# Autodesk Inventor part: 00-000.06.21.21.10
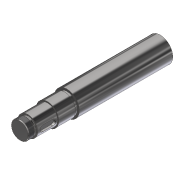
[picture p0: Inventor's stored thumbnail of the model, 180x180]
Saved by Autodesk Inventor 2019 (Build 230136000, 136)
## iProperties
Created: 2019-01
Part Number: 00-000.06.21.21.10
Material: Steel, Mild
Document SubType Name: Modeling
Designer: m.vorobev
Density: 7.85 g/cm^3
Appearance: Semi-Polished
Author: m.vorobev
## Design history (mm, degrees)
sketch "Sketch1"
  geometry: L1 (0, 0)-(18, 0); L2 (18, 0)-(18, -11.5); L3 (18, -11.5)-(0, -11.5); L4 (0, -11.5)-(0, 0); L5 (0, -16)-(20, -16); L6 (20, -16)-(20, -55.5); L7 (20, -55.5)-(0, -55.5); L8 (0, -55.5)-(0, -16); L9 (0, -55.5)-(22.5, -55.5); L10 (22.5, -55.5)-(22.5, -89); L11 (22.5, -89)-(0, -89); L12 (0, -89)-(0, -55.5); L13 (0, -89)-(21, -89); L14 (21, -89)-(21, -94); L15 (21, -94)-(0, -94); L16 (0, -94)-(0, -89); L17 (0, -94)-(25, -94); L18 (25, -94)-(25, -280.744); L19 (25, -280.744)-(0, -280.744); L20 (0, -280.744)-(0, -94); L21 (18, -11.5)-(16.8, -12.7); L22 (16.8, -12.7)-(16.8, -16); L23 (0, -11.5)-(0, -16)
  constraints: 46 end point, 10 parallel, 6 perpendicular, 5 horizontal, 2 point on line, 1 collinear
  dimensions: "d0" = 36 diameter of L2 L4; "d1" = 16 distance between parallel lines of L5 L1; "d2" = 4.5 distance between parallel lines of L5 L3; "d3" = 33.6 diameter of L22 L4; "d4" = 45 deg angle of L2 L21; "d5" = 40 diameter of L6 L4; "d6" = 45 diameter of L10 L4; "d7" = 39.5 distance of L5.end L6.end; "d8" = 94 distance between parallel lines of L1 L17; "d9" = 42 diameter of L14 L4; "d10" = 50 diameter of L18 L4; "d11" = 5 distance of L13.end L14.end
revolve "Revolution1" sketch "Sketch1" stored, may be unused: angle "d12" = 90 deg
fillet "Fillet1" dims "d13" = 0.8
chamfer "Chamfer1" distance "d14" = 1.6; stored, may be unused: second distance "d15" = 2, angle "d16" = 45 deg
workplane "Work Plane1"
sketch "Sketch2"
  geometry: L1 (0, 14.75)-(0, -17.25); L2 (6, 8.75)-(6, -11.25); L3 (-6, -11.25)-(-6, 8.75); L4 (-20, 19.75)-(20, 19.75) reference; L5 (-22.5, -19.75)-(22.5, -19.75) reference; A1 r 6 centre (0, 8.75) between (6, 8.75) and (-6, 8.75); A2 r 6 centre (0, -11.25) between (-6, -11.25) and (6, -11.25); 2 further points
  constraints: 8 end point, 6 point on circle, 4 tangent, 2 centre point, 2 point on line, 1 midpoint, 1 parallel, 1 vertical, 1 vertical alignment
  dimensions: "d17" = 5 distance from line of L4 L1.start; "d18" = 6 radius of A1; "d19" = 2.5 distance from line of L5 L1.end
extrude "Extrusion1" cut sketch "Sketch2" distance "d20" = 5; taper "d21" = 0 deg
thread "Thread1" dims "d22" = 10, "d23" = 0
body "Solid1"
